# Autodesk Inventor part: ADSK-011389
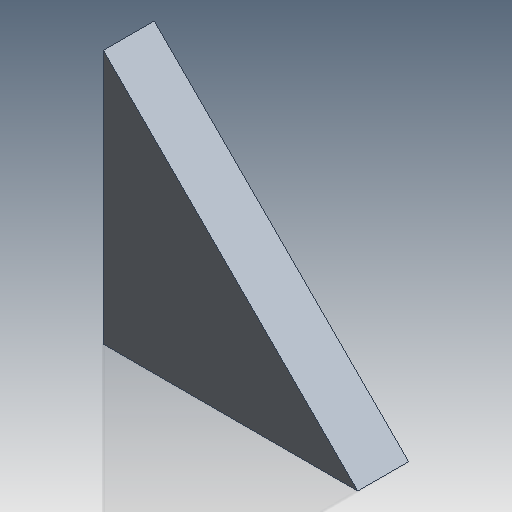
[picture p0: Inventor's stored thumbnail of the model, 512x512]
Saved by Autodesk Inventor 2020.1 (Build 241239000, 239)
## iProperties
Created: 2000-01
Part Number: ADSK-011389
Material: Pearson Aluminium
Document SubType Name: Modeling
Designer: sspink
Density: 2.71 g/cm^3
Appearance: Pearson-Aluminum
Mass: 33.875 g
Surface Area: 42.0711 cm^2
Volume: 12.5 cm^3
Control State: 0
Checked Out: False
Master: False
Shininess: 35.0
Length Units: 11269
Angle Units: 11279
Time Units: 11290
Mass Units: 11283
Length Display Precision: 3
Angle Display Precision: 2
Compacted: True
Cutlength: 2
Material Desc: FLAT,ALUM,0.375X02.000
Material_number: A084024
Dimensions: 50x50x10 mm
Mass: 0,034 kg
DocNumber: ADSK-011389.ipt
Folder: 01 - Themengebiete\Simplification\01 - Packaging machine\
VDS_Category: 3D Komponenten
Density: 2.71
Volumn: 12.290298
Area: 42.32675516425469
PropertySet Name: Model Information
Author: sspink
Revision Number: -
Title: stiffening plate
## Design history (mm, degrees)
node "Solide1"
  node "Extrusion1" dims "d2" = 10, "d3" = 0
sketch "Sketch1"
  geometry: L1 (0, 0)-(0, 50); L2 (0, 50)-(50, 0); L3 (50, 0)-(0, 0)
  constraints: 6 end point, 1 perpendicular, 1 vertical
  dimensions: "d0" = 50 distance of L1.start L1.end; "d1" = 50 distance of L2.end L1.start (= d0)
node "Corps solides"
node "Corps surfaciques"
